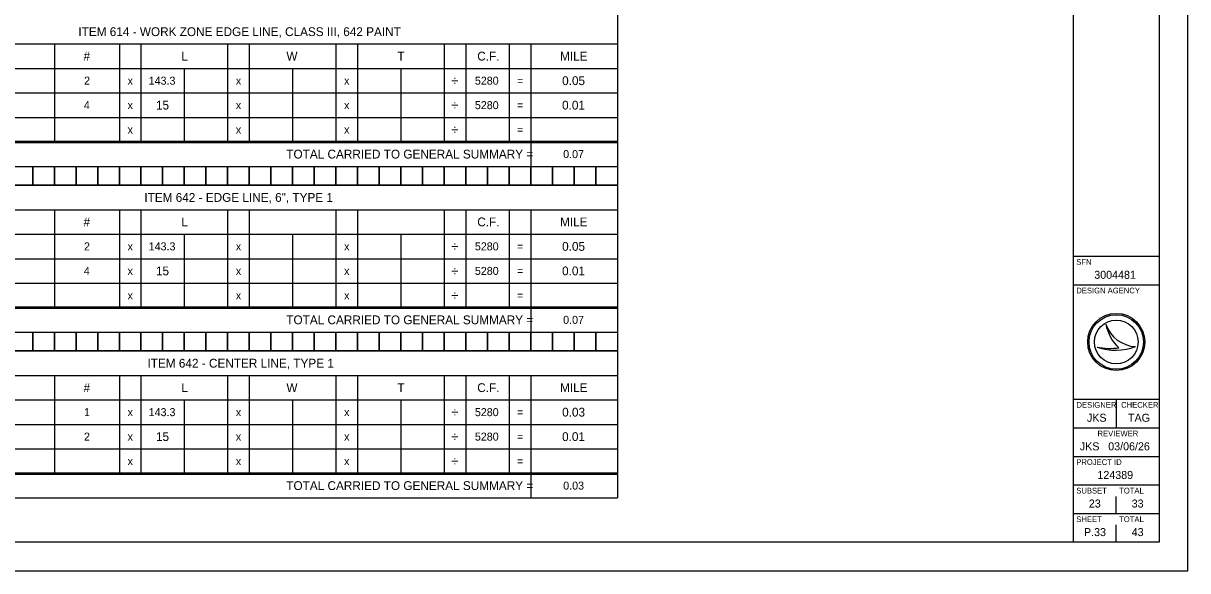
# Model space of a CAD drawing. Extents: x 0 to 34, y 0 to 22.
# Drawn here: x 13.63 to 34, y 0 to 9.57 of the extents above; entities that cross this region are included whole.
import ezdxf

# ---------------------------------------------------------------- set-up
doc = ezdxf.new("R2010")
doc.units = 0
for name, color, linetype in [('Default', 7, 'Continuous'), ('SH_Border', 7, 'Continuous'), ('SH_Cut_Line', 7, 'Continuous'), ('SH_Data', 7, 'Continuous')]:
    doc.layers.add(name, color=color, linetype=linetype)

msp = doc.modelspace()

# ---------------------------------------------------------------- linework, layer by layer
at = {"layer": 'Default'}
for p, q in [((24.021, 10.41), (24.021, 7.489)), ((10.762, 9.213), (24.021, 9.213)), ((14.171, 9.213), (14.171, 7.511)), ((15.308, 9.213), (15.308, 7.511)), ((15.686, 9.213), (15.686, 7.511)), ((17.202, 9.213), (17.202, 7.511)), ((17.581, 9.213), (17.581, 7.511)), ((19.096, 9.213), (19.096, 7.511)), ((19.475, 9.213), (19.475, 7.511)), ((20.99, 9.213), (20.99, 7.511)), ((21.369, 9.213), (21.369, 7.511)), ((22.126, 9.213), (22.126, 7.511)), ((22.505, 9.213), (22.505, 7.511)), ((10.762, 8.785), (24.021, 8.785)), ((16.444, 8.785), (16.444, 7.511)), ((18.338, 8.785), (18.338, 7.511)), ((20.232, 8.785), (20.232, 7.511)), ((10.762, 8.356), (24.021, 8.356)), ((10.762, 7.928), (24.021, 7.928)), ((10.762, 7.511), (24.021, 7.511)), ((10.762, 7.489), (24.021, 7.489)), ((22.505, 7.489), (22.505, 7.072)), ((24.021, 7.511), (24.021, 4.59)), ((10.762, 7.072), (24.021, 7.072)), ((10.762, 6.742), (24.021, 6.742)), ((10.762, 6.314), (24.021, 6.314)), ((14.171, 6.314), (14.171, 4.612)), ((15.308, 6.314), (15.308, 4.612)), ((15.686, 6.314), (15.686, 4.612)), ((17.202, 6.314), (17.202, 4.612)), ((17.581, 6.314), (17.581, 4.612)), ((19.096, 6.314), (19.096, 4.612)), ((19.475, 6.314), (19.475, 4.612)), ((20.99, 6.314), (20.99, 4.612)), ((21.369, 6.314), (21.369, 4.612)), ((22.126, 6.314), (22.126, 4.612)), ((22.505, 6.314), (22.505, 4.612)), ((10.762, 5.886), (24.021, 5.886)), ((16.444, 5.886), (16.444, 4.612)), ((18.338, 5.886), (18.338, 4.612)), ((20.232, 5.886), (20.232, 4.612)), ((10.762, 5.457), (24.021, 5.457)), ((10.762, 5.029), (24.021, 5.029)), ((10.762, 4.612), (24.021, 4.612)), ((10.762, 4.59), (24.021, 4.59)), ((22.505, 4.59), (22.505, 4.173)), ((24.021, 4.612), (24.021, 1.691)), ((10.762, 4.173), (24.021, 4.173)), ((10.762, 3.843), (24.021, 3.843)), ((10.762, 3.415), (24.021, 3.415)), ((14.171, 3.415), (14.171, 1.713)), ((15.308, 3.415), (15.308, 1.713)), ((15.686, 3.415), (15.686, 1.713)), ((17.202, 3.415), (17.202, 1.713)), ((17.581, 3.415), (17.581, 1.713)), ((19.096, 3.415), (19.096, 1.713)), ((19.475, 3.415), (19.475, 1.713)), ((20.99, 3.415), (20.99, 1.713)), ((21.369, 3.415), (21.369, 1.713)), ((22.126, 3.415), (22.126, 1.713)), ((22.505, 3.415), (22.505, 1.713)), ((10.762, 2.987), (24.021, 2.987)), ((16.444, 2.987), (16.444, 1.713)), ((18.338, 2.987), (18.338, 1.713)), ((20.232, 2.987), (20.232, 1.713)), ((10.762, 2.559), (24.021, 2.559)), ((10.762, 2.13), (24.021, 2.13)), ((10.762, 1.713), (24.021, 1.713)), ((10.762, 1.691), (24.021, 1.691)), ((22.505, 1.691), (22.505, 1.274)), ((24.021, 1.713), (24.021, 1.274)), ((10.762, 1.274), (24.021, 1.274))]:
    msp.add_line(p, q, dxfattribs=at)
for points in [[(13.414, 7.072), (13.792, 7.072), (13.792, 6.742), (13.414, 6.742)], [(13.792, 7.072), (14.171, 7.072), (14.171, 6.742), (13.792, 6.742)], [(14.171, 7.072), (14.55, 7.072), (14.55, 6.742), (14.171, 6.742)], [(14.55, 7.072), (14.929, 7.072), (14.929, 6.742), (14.55, 6.742)], [(14.929, 7.072), (15.308, 7.072), (15.308, 6.742), (14.929, 6.742)], [(15.308, 7.072), (15.686, 7.072), (15.686, 6.742), (15.308, 6.742)], [(15.686, 7.072), (16.065, 7.072), (16.065, 6.742), (15.686, 6.742)], [(16.065, 7.072), (16.444, 7.072), (16.444, 6.742), (16.065, 6.742)], [(16.444, 7.072), (16.823, 7.072), (16.823, 6.742), (16.444, 6.742)], [(16.823, 7.072), (17.202, 7.072), (17.202, 6.742), (16.823, 6.742)], [(17.202, 7.072), (17.581, 7.072), (17.581, 6.742), (17.202, 6.742)], [(17.581, 7.072), (17.959, 7.072), (17.959, 6.742), (17.581, 6.742)], [(17.959, 7.072), (18.338, 7.072), (18.338, 6.742), (17.959, 6.742)], [(18.338, 7.072), (18.717, 7.072), (18.717, 6.742), (18.338, 6.742)], [(18.717, 7.072), (19.096, 7.072), (19.096, 6.742), (18.717, 6.742)], [(19.096, 7.072), (19.475, 7.072), (19.475, 6.742), (19.096, 6.742)], [(19.475, 7.072), (19.854, 7.072), (19.854, 6.742), (19.475, 6.742)], [(19.854, 7.072), (20.232, 7.072), (20.232, 6.742), (19.854, 6.742)], [(20.232, 7.072), (20.611, 7.072), (20.611, 6.742), (20.232, 6.742)], [(20.611, 7.072), (20.99, 7.072), (20.99, 6.742), (20.611, 6.742)], [(20.99, 7.072), (21.369, 7.072), (21.369, 6.742), (20.99, 6.742)], [(21.369, 7.072), (21.748, 7.072), (21.748, 6.742), (21.369, 6.742)], [(21.748, 7.072), (22.126, 7.072), (22.126, 6.742), (21.748, 6.742)], [(22.126, 7.072), (22.505, 7.072), (22.505, 6.742), (22.126, 6.742)], [(22.505, 7.072), (22.884, 7.072), (22.884, 6.742), (22.505, 6.742)], [(22.884, 7.072), (23.263, 7.072), (23.263, 6.742), (22.884, 6.742)], [(23.263, 7.072), (23.642, 7.072), (23.642, 6.742), (23.263, 6.742)], [(23.642, 7.072), (24.021, 7.072), (24.021, 6.742), (23.642, 6.742)], [(13.414, 4.173), (13.792, 4.173), (13.792, 3.843), (13.414, 3.843)], [(13.792, 4.173), (14.171, 4.173), (14.171, 3.843), (13.792, 3.843)], [(14.171, 4.173), (14.55, 4.173), (14.55, 3.843), (14.171, 3.843)], [(14.55, 4.173), (14.929, 4.173), (14.929, 3.843), (14.55, 3.843)], [(14.929, 4.173), (15.308, 4.173), (15.308, 3.843), (14.929, 3.843)], [(15.308, 4.173), (15.686, 4.173), (15.686, 3.843), (15.308, 3.843)], [(15.686, 4.173), (16.065, 4.173), (16.065, 3.843), (15.686, 3.843)], [(16.065, 4.173), (16.444, 4.173), (16.444, 3.843), (16.065, 3.843)], [(16.444, 4.173), (16.823, 4.173), (16.823, 3.843), (16.444, 3.843)], [(16.823, 4.173), (17.202, 4.173), (17.202, 3.843), (16.823, 3.843)], [(17.202, 4.173), (17.581, 4.173), (17.581, 3.843), (17.202, 3.843)], [(17.581, 4.173), (17.959, 4.173), (17.959, 3.843), (17.581, 3.843)], [(17.959, 4.173), (18.338, 4.173), (18.338, 3.843), (17.959, 3.843)], [(18.338, 4.173), (18.717, 4.173), (18.717, 3.843), (18.338, 3.843)], [(18.717, 4.173), (19.096, 4.173), (19.096, 3.843), (18.717, 3.843)], [(19.096, 4.173), (19.475, 4.173), (19.475, 3.843), (19.096, 3.843)], [(19.475, 4.173), (19.854, 4.173), (19.854, 3.843), (19.475, 3.843)], [(19.854, 4.173), (20.232, 4.173), (20.232, 3.843), (19.854, 3.843)], [(20.232, 4.173), (20.611, 4.173), (20.611, 3.843), (20.232, 3.843)], [(20.611, 4.173), (20.99, 4.173), (20.99, 3.843), (20.611, 3.843)], [(20.99, 4.173), (21.369, 4.173), (21.369, 3.843), (20.99, 3.843)], [(21.369, 4.173), (21.748, 4.173), (21.748, 3.843), (21.369, 3.843)], [(21.748, 4.173), (22.126, 4.173), (22.126, 3.843), (21.748, 3.843)], [(22.126, 4.173), (22.505, 4.173), (22.505, 3.843), (22.126, 3.843)], [(22.505, 4.173), (22.884, 4.173), (22.884, 3.843), (22.505, 3.843)], [(22.884, 4.173), (23.263, 4.173), (23.263, 3.843), (22.884, 3.843)], [(23.263, 4.173), (23.642, 4.173), (23.642, 3.843), (23.263, 3.843)], [(23.642, 4.173), (24.021, 4.173), (24.021, 3.843), (23.642, 3.843)]]:
    msp.add_lwpolyline(points, close=True, dxfattribs=at)
at = {"layer": 'SH_Border'}
for p, q in [((32, 0.5), (32, 21.5)), ((32, 5.5), (33.5, 5.5)), ((32, 5), (33.5, 5)), ((32, 3), (33.5, 3)), ((32.75, 3), (32.75, 2.5)), ((32, 2.5), (33.5, 2.5)), ((32, 2), (33.5, 2)), ((32, 1.5), (33.5, 1.5)), ((32, 1), (33.5, 1))]:
    msp.add_line(p, q, dxfattribs=at)
msp.add_lwpolyline([(1.5, 21.5), (33.5, 21.5), (33.5, 0.5), (1.5, 0.5)], close=True, dxfattribs=at)
at = {"layer": 'SH_Cut_Line'}
msp.add_lwpolyline([(0, 0), (34, 0), (34, 22), (0, 22)], close=True, dxfattribs=at)
at = {"layer": 'SH_Data'}
for p, q in [((32.567, 4.31), (32.567, 4.31)), ((32.417, 3.91), (32.417, 3.91)), ((32.75, 4), (32.75, 4)), ((33.087, 3.919), (33.087, 3.919)), ((32.75, 1), (32.75, 1.3)), ((32.375, 0.675), (32.375, 0.675)), ((32.75, 0.5), (32.75, 0.8))]:
    msp.add_line(p, q, dxfattribs=at)
for radius in [0.5, 0.477, 0.477, 0.382]:
    msp.add_circle((32.75, 4), radius, dxfattribs=at)
for centre, radius, start, end in [((33.116, 4.498), 0.58, 198.9257, 198.9319), ((33.347, 4.47), 0.796, 191.6379, 191.6421), ((33.116, 4.498), 0.58, 198.9319, 267.1657), ((33.347, 4.47), 0.796, 191.6421, 226.0947), ((32.739, 4.87), 1.013, 251.4576, 290.0832), ((32.648, 5.154), 1.266, 259.4964, 259.4995), ((32.739, 4.87), 1.013, 251.4527, 251.4576), ((32.648, 5.154), 1.266, 259.4995, 276.6672)]:
    msp.add_arc(centre, radius, start, end, dxfattribs=at)

# ---------------------------------------------------------------- texts
at = {"layer": 'Default'}
for s, height, p in [('ITEM 614 - WORK ZONE EDGE LINE, CLASS III, 642 PAINT', 0.154, (14.591, 9.35)), ('#', 0.154, (14.681, 8.922)), ('L', 0.154, (16.394, 8.922)), ('W', 0.154, (18.231, 8.922)), ('T', 0.154, (20.173, 8.922)), ('C.F.', 0.154, (21.57, 8.922)), ('MILE', 0.154, (23.019, 8.922)), ('2', 0.14, (14.69, 8.5)), ('x', 0.14, (15.452, 8.5)), ('143.3', 0.14, (15.821, 8.5)), ('x', 0.14, (17.346, 8.5)), ('x', 0.14, (19.24, 8.5)), ('÷', 0.168, (21.117, 8.486)), ('5280', 0.14, (21.528, 8.5)), ('=', 0.14, (22.266, 8.5)), ('0.05', 0.154, (23.055, 8.493)), ('4', 0.14, (14.687, 8.072)), ('x', 0.14, (15.452, 8.072)), ('15', 0.154, (15.949, 8.065)), ('x', 0.14, (17.346, 8.072)), ('x', 0.14, (19.24, 8.072)), ('÷', 0.168, (21.117, 8.058)), ('5280', 0.14, (21.528, 8.072)), ('=', 0.14, (22.266, 8.072)), ('0.01', 0.154, (23.054, 8.065)), ('x', 0.14, (15.452, 7.644)), ('x', 0.14, (17.346, 7.644)), ('x', 0.14, (19.24, 7.644)), ('÷', 0.168, (21.117, 7.63)), ('=', 0.14, (22.266, 7.644)), ('TOTAL CARRIED TO GENERAL SUMMARY =', 0.154, (18.229, 7.209)), ('0.07', 0.14, (23.073, 7.216)), ('ITEM 642 - EDGE LINE, 6", TYPE 1', 0.154, (15.745, 6.451)), ('#', 0.154, (14.681, 6.023)), ('L', 0.154, (16.394, 6.023)), ('C.F.', 0.154, (21.57, 6.023)), ('MILE', 0.154, (23.019, 6.023)), ('2', 0.14, (14.69, 5.602)), ('x', 0.14, (15.452, 5.602)), ('143.3', 0.14, (15.821, 5.602)), ('x', 0.14, (17.346, 5.602)), ('x', 0.14, (19.24, 5.602)), ('÷', 0.168, (21.117, 5.588)), ('5280', 0.14, (21.528, 5.602)), ('0.05', 0.154, (23.055, 5.595)), ('=', 0.14, (22.266, 5.602)), ('4', 0.14, (14.687, 5.173)), ('15', 0.154, (15.949, 5.166)), ('5280', 0.14, (21.528, 5.173)), ('0.01', 0.154, (23.054, 5.166)), ('x', 0.14, (15.452, 5.173)), ('x', 0.14, (17.346, 5.173)), ('x', 0.14, (19.24, 5.173)), ('÷', 0.168, (21.117, 5.159)), ('=', 0.14, (22.266, 5.173)), ('x', 0.14, (15.452, 4.745)), ('x', 0.14, (17.346, 4.745)), ('x', 0.14, (19.24, 4.745)), ('÷', 0.168, (21.117, 4.731)), ('=', 0.14, (22.266, 4.745)), ('TOTAL CARRIED TO GENERAL SUMMARY =', 0.154, (18.229, 4.31)), ('0.07', 0.14, (23.073, 4.317)), ('ITEM 642 - CENTER LINE, TYPE 1', 0.154, (15.8, 3.552)), ('#', 0.154, (14.681, 3.124)), ('L', 0.154, (16.394, 3.124)), ('W', 0.154, (18.231, 3.124)), ('T', 0.154, (20.173, 3.124)), ('C.F.', 0.154, (21.57, 3.124)), ('MILE', 0.154, (23.019, 3.124)), ('1', 0.14, (14.69, 2.703)), ('x', 0.14, (15.452, 2.703)), ('143.3', 0.14, (15.821, 2.703)), ('x', 0.14, (17.346, 2.703)), ('x', 0.14, (19.24, 2.703)), ('÷', 0.168, (21.117, 2.689)), ('5280', 0.14, (21.528, 2.703)), ('=', 0.14, (22.266, 2.703)), ('0.03', 0.154, (23.055, 2.696)), ('2', 0.14, (14.69, 2.275)), ('x', 0.14, (15.452, 2.275)), ('15', 0.154, (15.949, 2.268)), ('x', 0.14, (17.346, 2.275)), ('x', 0.14, (19.24, 2.275)), ('÷', 0.168, (21.117, 2.261)), ('5280', 0.14, (21.528, 2.275)), ('=', 0.14, (22.266, 2.275)), ('0.01', 0.154, (23.054, 2.268)), ('x', 0.14, (15.452, 1.846)), ('x', 0.14, (17.346, 1.846)), ('x', 0.14, (19.24, 1.846)), ('÷', 0.168, (21.117, 1.832)), ('=', 0.14, (22.266, 1.846)), ('TOTAL CARRIED TO GENERAL SUMMARY =', 0.154, (18.229, 1.411)), ('0.03', 0.14, (23.074, 1.418))]:
    msp.add_text(s, height=height, dxfattribs=at).set_placement(p)
at = {"layer": 'SH_Data'}
for s, height, p in [('SFN', 0.1, (32.05, 5.35)), ('3004481', 0.14, (32.365, 5.105)), ('DESIGN AGENCY', 0.1, (32.05, 4.85)), ('DESIGNER', 0.1, (32.054, 2.85)), ('CHECKER', 0.1, (32.835, 2.85)), ('JKS', 0.14, (32.237, 2.605)), ('TAG', 0.14, (32.955, 2.605)), ('REVIEWER', 0.1, (32.422, 2.35)), ('JKS', 0.14, (32.112, 2.105)), ('03/06/26', 0.14, (32.609, 2.105)), ('PROJECT ID', 0.1, (32.05, 1.85)), ('124389', 0.14, (32.42, 1.605)), ('SUBSET', 0.1, (32.05, 1.35)), ('TOTAL', 0.1, (32.8, 1.35)), ('23', 0.14, (32.27, 1.105)), ('33', 0.14, (33.02, 1.105)), ('SHEET', 0.1, (32.05, 0.85)), ('TOTAL', 0.1, (32.8, 0.85)), ('P.33', 0.14, (32.185, 0.605)), ('43', 0.14, (33.02, 0.605))]:
    msp.add_text(s, height=height, dxfattribs=at).set_placement(p)

doc.saveas('drawing.dxf')
